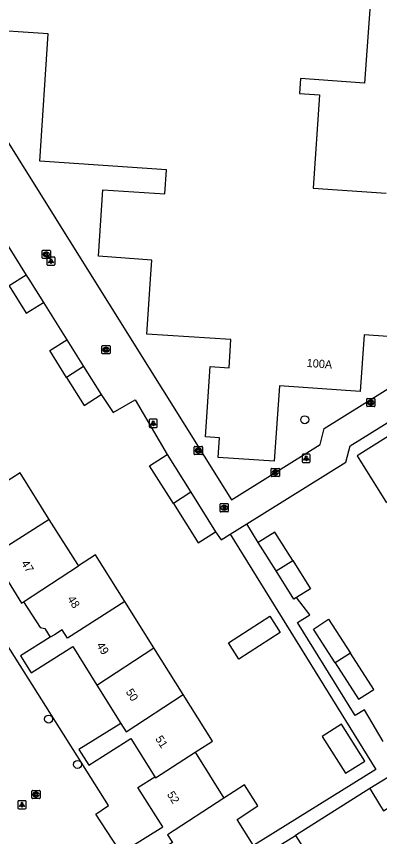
# Model space of a CAD drawing. Extents: x 158461 to 159795, y 387220 to 388672.
# Drawn here: x 158888.2 to 158932.6, y 387931.9 to 388032.1 of the extents above; entities that cross this region are included whole.
import ezdxf

# ---------------------------------------------------------------- set-up
doc = ezdxf.new("R2010")
doc.units = 0
for name, color, linetype in [('IMGEO_Boom', 7, 'Continuous'), ('IMGEO_Kolk', 7, 'Continuous'), ('IMGEO_Lichtpunt', 7, 'Continuous'), ('IMGEO_Pand', 7, 'Continuous'), ('IMGEO_Pand_nummerreeks', 7, 'Continuous'), ('IMGEO_Rijbaan_lokaal_open', 7, 'Continuous'), ('IMGEO_Rioolput', 7, 'Continuous'), ('IMGEO_Voetpad_open', 7, 'Continuous')]:
    doc.layers.add(name, color=color, linetype=linetype)

msp = doc.modelspace()

# ---------------------------------------------------------------- linework, layer by layer
at = {"layer": 'IMGEO_Boom'}
for centre in [(158923.44, 387982.83), (158892.12, 387946.23), (158895.66, 387940.69)]:
    msp.add_circle(centre, 0.489, dxfattribs=at)
at = {"layer": 'IMGEO_Kolk'}
for p, q in [((158891.34, 388002.62), (158891.34, 388003.48)), ((158891.41, 388003.55), (158892.27, 388003.55)), ((158891.85, 388002.77), (158891.82, 388002.77)), ((158891.83, 388003.33), (158891.85, 388003.33)), ((158892.34, 388003.48), (158892.34, 388002.62)), ((158892.27, 388002.55), (158891.41, 388002.55)), ((158898.65, 387990.96), (158898.65, 387991.82)), ((158898.72, 387991.89), (158899.57, 387991.89)), ((158899.13, 387991.67), (158899.16, 387991.67)), ((158899.65, 387991.82), (158899.65, 387990.96)), ((158899.57, 387990.89), (158898.72, 387990.89)), ((158899.16, 387991.11), (158899.13, 387991.11)), ((158931.02, 387984.51), (158931.02, 387985.36)), ((158931.1, 387985.44), (158931.95, 387985.44)), ((158931.51, 387985.21), (158931.54, 387985.21)), ((158931.53, 387984.66), (158931.51, 387984.66)), ((158932.02, 387985.36), (158932.02, 387984.51)), ((158931.95, 387984.43), (158931.1, 387984.43)), ((158910.02, 387979.57), (158910.87, 387979.57)), ((158909.94, 387978.64), (158909.94, 387979.49)), ((158910.87, 387978.57), (158910.02, 387978.57)), ((158910.43, 387979.35), (158910.45, 387979.35)), ((158910.45, 387978.79), (158910.43, 387978.79)), ((158910.94, 387979.49), (158910.94, 387978.64)), ((158919.35, 387975.95), (158919.35, 387976.81)), ((158919.42, 387976.88), (158920.28, 387976.88)), ((158919.84, 387976.66), (158919.86, 387976.66)), ((158920.35, 387976.81), (158920.35, 387975.95)), ((158920.28, 387975.88), (158919.42, 387975.88)), ((158919.86, 387976.1), (158919.83, 387976.1)), ((158890.08, 387936.59), (158890.08, 387937.44)), ((158890.15, 387937.52), (158891.01, 387937.52)), ((158891.08, 387937.44), (158891.08, 387936.59)), ((158891.01, 387936.52), (158890.15, 387936.52)), ((158890.59, 387936.74), (158890.56, 387936.74)), ((158890.57, 387937.3), (158890.59, 387937.3))]:
    msp.add_line(p, q, dxfattribs=at)
for points in [[(158891.34, 388002.62), (158891.34, 388003.48)], [(158891.41, 388003.55), (158892.27, 388003.55)], [(158891.66, 388003.25), (158891.78, 388003.25), (158891.78, 388003.1), (158891.91, 388003.25), (158892.08, 388003.25), (158891.93, 388003.1), (158892.08, 388002.85), (158891.93, 388002.85), (158891.85, 388003.01), (158891.78, 388002.95), (158891.78, 388002.85), (158891.66, 388002.85), (158891.66, 388003.25)], [(158892.34, 388003.48), (158892.34, 388002.62)], [(158892.27, 388002.55), (158891.41, 388002.55)], [(158898.65, 387990.96), (158898.65, 387991.82)], [(158898.72, 387991.89), (158899.57, 387991.89)], [(158898.97, 387991.59), (158899.09, 387991.59), (158899.09, 387991.44), (158899.22, 387991.59), (158899.38, 387991.59), (158899.24, 387991.44), (158899.39, 387991.19), (158899.24, 387991.19), (158899.15, 387991.36), (158899.09, 387991.29), (158899.09, 387991.19), (158898.97, 387991.19), (158898.97, 387991.59)], [(158899.65, 387991.82), (158899.65, 387990.96)], [(158899.57, 387990.89), (158898.72, 387990.89)], [(158931.02, 387984.51), (158931.02, 387985.36)], [(158931.1, 387985.44), (158931.95, 387985.44)], [(158931.34, 387985.13), (158931.47, 387985.13), (158931.47, 387984.98), (158931.6, 387985.13), (158931.76, 387985.13), (158931.61, 387984.98), (158931.77, 387984.73), (158931.61, 387984.73), (158931.53, 387984.9), (158931.47, 387984.83), (158931.47, 387984.73), (158931.34, 387984.73), (158931.34, 387985.13)], [(158932.02, 387985.36), (158932.02, 387984.51)], [(158931.95, 387984.43), (158931.1, 387984.43)], [(158910.02, 387979.57), (158910.87, 387979.57)], [(158909.94, 387978.64), (158909.94, 387979.49)], [(158910.87, 387978.57), (158910.02, 387978.57)], [(158910.26, 387979.27), (158910.39, 387979.27), (158910.39, 387979.12), (158910.51, 387979.27), (158910.68, 387979.27), (158910.53, 387979.12), (158910.69, 387978.87), (158910.53, 387978.87), (158910.45, 387979.03), (158910.39, 387978.96), (158910.39, 387978.87), (158910.26, 387978.87), (158910.26, 387979.27)], [(158910.94, 387979.49), (158910.94, 387978.64)], [(158919.35, 387975.95), (158919.35, 387976.81)], [(158919.42, 387976.88), (158920.28, 387976.88)], [(158919.67, 387976.58), (158919.79, 387976.58), (158919.79, 387976.43), (158919.92, 387976.58), (158920.09, 387976.58), (158919.94, 387976.43), (158920.09, 387976.18), (158919.94, 387976.18), (158919.86, 387976.35), (158919.79, 387976.28), (158919.79, 387976.18), (158919.67, 387976.18), (158919.67, 387976.58)], [(158920.35, 387976.81), (158920.35, 387975.95)], [(158920.28, 387975.88), (158919.42, 387975.88)], [(158890.08, 387936.59), (158890.08, 387937.44)], [(158890.15, 387937.52), (158891.01, 387937.52)], [(158891.08, 387937.44), (158891.08, 387936.59)], [(158891.01, 387936.52), (158890.15, 387936.52)], [(158890.4, 387937.22), (158890.52, 387937.22), (158890.52, 387937.07), (158890.65, 387937.22), (158890.82, 387937.22), (158890.67, 387937.07), (158890.82, 387936.82), (158890.67, 387936.82), (158890.59, 387936.98), (158890.52, 387936.92), (158890.52, 387936.82), (158890.4, 387936.82), (158890.4, 387937.22)]]:
    msp.add_lwpolyline(points, dxfattribs=at)
for centre, start, end in [((158891.42, 388003.47), 91.552, 178.448), ((158891.42, 388003.47), 91.552, 178.448), ((158891.42, 388002.63), 181.552, 268.448), ((158891.42, 388002.63), 181.552, 268.448), ((158892.26, 388003.47), 1.552, 88.448), ((158892.26, 388003.47), 1.552, 88.448), ((158892.26, 388002.63), 271.552, 358.448), ((158892.26, 388002.63), 271.552, 358.448), ((158898.72, 387991.82), 91.552, 178.448), ((158898.72, 387991.82), 91.552, 178.448), ((158899.57, 387991.82), 1.552, 88.448), ((158899.57, 387991.82), 1.552, 88.448), ((158898.72, 387990.97), 181.552, 268.448), ((158898.72, 387990.97), 181.552, 268.448), ((158899.57, 387990.97), 271.552, 358.448), ((158899.57, 387990.97), 271.552, 358.448), ((158931.1, 387985.36), 91.552, 178.448), ((158931.1, 387985.36), 91.552, 178.448), ((158931.95, 387985.36), 1.552, 88.448), ((158931.95, 387985.36), 1.552, 88.448), ((158931.1, 387984.51), 181.552, 268.448), ((158931.1, 387984.51), 181.552, 268.448), ((158931.95, 387984.51), 271.552, 358.448), ((158931.95, 387984.51), 271.552, 358.448), ((158910.02, 387979.49), 91.552, 178.448), ((158910.02, 387979.49), 91.552, 178.448), ((158910.87, 387979.49), 1.552, 88.448), ((158910.87, 387979.49), 1.552, 88.448), ((158910.02, 387978.64), 181.552, 268.448), ((158910.02, 387978.64), 181.552, 268.448), ((158910.87, 387978.64), 271.552, 358.448), ((158910.87, 387978.64), 271.552, 358.448), ((158919.43, 387976.81), 91.552, 178.448), ((158919.43, 387976.81), 91.552, 178.448), ((158920.27, 387976.81), 1.552, 88.448), ((158920.27, 387976.81), 1.552, 88.448), ((158919.43, 387975.96), 181.552, 268.448), ((158919.43, 387975.96), 181.552, 268.448), ((158920.27, 387975.96), 271.552, 358.448), ((158920.27, 387975.96), 271.552, 358.448), ((158890.15, 387937.44), 91.552, 178.448), ((158890.15, 387937.44), 91.552, 178.448), ((158891, 387937.44), 1.552, 88.448), ((158891, 387937.44), 1.552, 88.448), ((158890.15, 387936.59), 181.552, 268.448), ((158890.15, 387936.59), 181.552, 268.448), ((158891, 387936.59), 271.552, 358.448), ((158891, 387936.59), 271.552, 358.448)]:
    msp.add_arc(centre, 0.0765, start, end, dxfattribs=at)
for centre, major_axis, ratio, start_param, end_param in [((158891.83, 388003.05), (-0.387, 0.002), 0.722429, 4.712389, 7.853982), ((158891.85, 388003.05), (-0.39, 0.002), 0.717154, 1.570796, 4.712389), ((158899.13, 387991.39), (-0.387, 0.002), 0.722429, 4.712389, 7.853982), ((158899.16, 387991.39), (-0.39, 0.002), 0.717154, 1.570796, 4.712389), ((158931.51, 387984.93), (-0.387, 0.002), 0.722429, 4.712389, 7.853982), ((158931.53, 387984.93), (-0.39, 0.002), 0.717154, 1.570796, 4.712389), ((158910.43, 387979.07), (-0.387, 0.002), 0.722429, 4.712389, 7.853982), ((158910.45, 387979.07), (-0.39, 0.002), 0.717154, 1.570796, 4.712389), ((158919.84, 387976.38), (-0.387, 0.002), 0.722429, 4.712389, 7.853982), ((158919.86, 387976.38), (-0.39, 0.002), 0.717154, 1.570796, 4.712389), ((158890.57, 387937.02), (-0.387, 0.002), 0.722429, 4.712389, 7.853982), ((158890.59, 387937.02), (-0.39, 0.002), 0.717154, 1.570796, 4.712389)]:
    msp.add_ellipse(centre, major_axis=major_axis, ratio=ratio, start_param=start_param, end_param=end_param, dxfattribs=at)
at = {"layer": 'IMGEO_Lichtpunt'}
for p, q in [((158891.91, 388002.62), (158891.91, 388001.82)), ((158891.91, 388002.62), (158891.91, 388001.82)), ((158892.81, 388002.72), (158892.01, 388002.72)), ((158892.81, 388002.72), (158892.01, 388002.72)), ((158892.91, 388001.82), (158892.91, 388002.62)), ((158892.91, 388001.82), (158892.91, 388002.62)), ((158892.01, 388001.72), (158892.81, 388001.72)), ((158892.01, 388001.72), (158892.81, 388001.72)), ((158904.42, 387982.8), (158904.42, 387981.99)), ((158904.42, 387982.8), (158904.42, 387981.99)), ((158905.32, 387982.89), (158904.51, 387982.89)), ((158905.32, 387982.89), (158904.51, 387982.89)), ((158905.42, 387981.99), (158905.42, 387982.8)), ((158905.42, 387981.99), (158905.42, 387982.8)), ((158904.51, 387981.9), (158905.32, 387981.9)), ((158904.51, 387981.9), (158905.32, 387981.9)), ((158924.02, 387978.61), (158923.22, 387978.61)), ((158924.02, 387978.61), (158923.22, 387978.61)), ((158923.12, 387978.51), (158923.12, 387977.71)), ((158923.12, 387978.51), (158923.12, 387977.71)), ((158923.22, 387977.61), (158924.02, 387977.61)), ((158923.22, 387977.61), (158924.02, 387977.61)), ((158924.12, 387977.71), (158924.12, 387978.51)), ((158924.12, 387977.71), (158924.12, 387978.51)), ((158888.38, 387936.16), (158888.38, 387935.36)), ((158888.38, 387936.16), (158888.38, 387935.36)), ((158889.28, 387936.26), (158888.47, 387936.26)), ((158889.28, 387936.26), (158888.47, 387936.26)), ((158889.38, 387935.36), (158889.38, 387936.16)), ((158889.38, 387935.36), (158889.38, 387936.16)), ((158888.47, 387935.26), (158889.28, 387935.26)), ((158888.47, 387935.26), (158889.28, 387935.26))]:
    msp.add_line(p, q, dxfattribs=at)
for points in [[(158892.29, 388002.29), (158892.33, 388002.26), (158892.14, 388002), (158892.1, 388002.03), (158892.29, 388002.29)], [(158892.39, 388002.24), (158892.44, 388002.24), (158892.44, 388001.92), (158892.39, 388001.92), (158892.39, 388002.24)], [(158892.5, 388002.26), (158892.54, 388002.29), (158892.72, 388002.02), (158892.69, 388002), (158892.5, 388002.26)], [(158904.79, 387982.46), (158904.83, 387982.43), (158904.65, 387982.17), (158904.61, 387982.2), (158904.79, 387982.46)], [(158904.9, 387982.41), (158904.94, 387982.41), (158904.94, 387982.09), (158904.9, 387982.09), (158904.9, 387982.41)], [(158905.01, 387982.43), (158905.04, 387982.46), (158905.23, 387982.2), (158905.19, 387982.17), (158905.01, 387982.43)], [(158923.5, 387978.18), (158923.54, 387978.15), (158923.35, 387977.89), (158923.31, 387977.91), (158923.5, 387978.18)], [(158923.6, 387978.13), (158923.65, 387978.13), (158923.65, 387977.81), (158923.6, 387977.81), (158923.6, 387978.13)], [(158923.71, 387978.15), (158923.75, 387978.18), (158923.93, 387977.91), (158923.9, 387977.89), (158923.71, 387978.15)], [(158888.75, 387935.83), (158888.79, 387935.8), (158888.6, 387935.54), (158888.57, 387935.56), (158888.75, 387935.83)], [(158888.85, 387935.78), (158888.9, 387935.78), (158888.9, 387935.46), (158888.85, 387935.46), (158888.85, 387935.78)], [(158888.96, 387935.8), (158889, 387935.83), (158889.19, 387935.56), (158889.15, 387935.54), (158888.96, 387935.8)]]:
    msp.add_lwpolyline(points, dxfattribs=at)
for centre in [(158892.41, 388002.42), (158904.92, 387982.6), (158923.62, 387978.31), (158888.88, 387935.96)]:
    msp.add_circle(centre, 0.0994, dxfattribs=at)
for centre, start, end in [((158892.01, 388002.62), 90, 180), ((158892.01, 388002.62), 90, 180), ((158892.81, 388002.62), 0, 90), ((158892.81, 388002.62), 0, 90), ((158892.01, 388001.82), 180, 270), ((158892.01, 388001.82), 180, 270), ((158892.81, 388001.82), 270, 0), ((158892.81, 388001.82), 270, 360), ((158904.51, 387982.8), 90, 180), ((158904.51, 387982.8), 90, 180), ((158905.32, 387982.8), 0, 90), ((158905.32, 387982.8), 0, 90), ((158904.51, 387981.99), 180, 270), ((158904.51, 387981.99), 180, 270), ((158905.32, 387981.99), 270, 0), ((158905.32, 387981.99), 270, 360), ((158923.22, 387978.51), 90, 180), ((158923.22, 387978.51), 90, 180), ((158924.02, 387978.51), 0, 90), ((158924.02, 387978.51), 0, 90), ((158923.22, 387977.71), 180, 270), ((158923.22, 387977.71), 180, 270), ((158924.02, 387977.71), 270, 0), ((158924.02, 387977.71), 270, 360), ((158888.47, 387936.16), 90, 180), ((158888.47, 387936.16), 90, 180), ((158889.28, 387936.16), 0, 90), ((158889.28, 387936.16), 0, 90), ((158888.47, 387935.36), 180, 270), ((158888.47, 387935.36), 180, 270), ((158889.28, 387935.36), 270, 0), ((158889.28, 387935.36), 270, 360)]:
    msp.add_arc(centre, 0.0946, start, end, dxfattribs=at)
at = {"layer": 'IMGEO_Pand'}
for points in [[(158931.89, 388039.84), (158930.75, 388023.98)], [(158940.55, 387992.52), (158930.7, 387993.22), (158930.21, 387986.3), (158920.36, 387986.99), (158919.71, 387977.75), (158912.85, 387978.23), (158913.01, 387980.61), (158911.29, 387980.73), (158911.9, 387989.32), (158914.19, 387989.16), (158914.42, 387992.64), (158904.14, 387993.31), (158904.58, 388000), (158904.74, 388002.35), (158898.21, 388002.82), (158898.76, 388010.94), (158906.33, 388010.43), (158906.55, 388013.39), (158891.04, 388014.45), (158892.07, 388030.01), (158883.53, 388030.56)], [(158930.75, 388023.98), (158922.93, 388024.56), (158922.8, 388022.72), (158925.26, 388022.53), (158924.47, 388011.14), (158933.39, 388010.52)], [(158887.17, 388004.03), (158889.38, 388000.51)], [(158889.38, 388000.51), (158887.3, 387999.19)], [(158889.38, 388000.51), (158889.7, 388000), (158891.49, 387997.15)], [(158887.3, 387999.19), (158889.4, 387995.84), (158891.49, 387997.15)], [(158894.32, 387988.01), (158892.26, 387991.29), (158894.36, 387992.6)], [(158894.36, 387992.6), (158896.4, 387989.35)], [(158896.4, 387989.35), (158894.32, 387988.01)], [(158896.4, 387989.35), (158898.57, 387985.91)], [(158894.32, 387988.01), (158896.47, 387984.59), (158898.57, 387985.91)], [(158940.49, 387977.03), (158936.85, 387982.81), (158929.85, 387978.4), (158933.45, 387972.68)], [(158907.39, 387972.57), (158904.47, 387977.21), (158906.62, 387978.56)], [(158906.62, 387978.56), (158909.51, 387973.96)], [(158892.21, 387970.65), (158888.64, 387976.33), (158886.62, 387975.02)], [(158909.51, 387973.96), (158907.39, 387972.57)], [(158909.51, 387973.96), (158912.55, 387969.12)], [(158907.39, 387972.57), (158910.4, 387967.77), (158912.55, 387969.12)], [(158892.21, 387970.65), (158885.17, 387966.2), (158885.82, 387965.16)], [(158895.78, 387964.96), (158895.68, 387965.12), (158892.21, 387970.65)], [(158921.97, 387965.61), (158919.79, 387969.08), (158917.77, 387967.82)], [(158919.94, 387964.35), (158917.77, 387967.82)], [(158901.43, 387960.62), (158897.85, 387966.31), (158895.78, 387964.96)], [(158919.94, 387964.35), (158921.97, 387965.61)], [(158921.97, 387965.61), (158924.13, 387962.17), (158922.44, 387961.1)], [(158885.82, 387965.16), (158888.8, 387960.42), (158889.04, 387960.58)], [(158889.04, 387960.58), (158895.78, 387964.96)], [(158922.44, 387961.1), (158922.11, 387960.9), (158919.94, 387964.35)], [(158889.04, 387960.58), (158891.08, 387957.44), (158891.65, 387957.3), (158892.32, 387956.23)], [(158901.43, 387960.62), (158894.42, 387956.13), (158893.78, 387957.15), (158892.83, 387956.55), (158892.32, 387956.23)], [(158905, 387954.93), (158901.43, 387960.62)], [(158919.16, 387958.81), (158920.44, 387956.84), (158915.39, 387953.57), (158914.11, 387955.55), (158919.16, 387958.81)], [(158927.15, 387953.13), (158924.5, 387957.24), (158926.37, 387958.45), (158929.05, 387954.29)], [(158892.32, 387956.23), (158888.69, 387953.95), (158889.98, 387951.89), (158895.07, 387955.09), (158898.02, 387950.39)], [(158898.02, 387950.39), (158905, 387954.93)], [(158908.57, 387949.25), (158905, 387954.93)], [(158929.05, 387954.29), (158927.15, 387953.13)], [(158927.15, 387953.13), (158930.03, 387948.67), (158931.9, 387949.87), (158929.05, 387954.29)], [(158898.02, 387950.39), (158900.96, 387945.71)], [(158900.96, 387945.71), (158901.6, 387944.68), (158908.57, 387949.25)], [(158910.03, 387942.18), (158912.17, 387943.53), (158908.57, 387949.25)], [(158900.96, 387945.71), (158895.84, 387942.5), (158897.03, 387940.61), (158902.17, 387943.85), (158905.11, 387939.17)], [(158925.59, 387944.12), (158928.44, 387939.61), (158930.8, 387941.11), (158927.96, 387945.61), (158925.59, 387944.12)], [(158905.11, 387939.17), (158905.18, 387939.06), (158910.03, 387942.18)], [(158910.03, 387942.18), (158913.56, 387936.56)], [(158935.28, 387940.13), (158931.41, 387937.73)], [(158907.29, 387931.15), (158902.98, 387928.44), (158901.78, 387930.36), (158906.08, 387933.06), (158903.05, 387937.88), (158905.11, 387939.17)], [(158917.18, 387930.8), (158915.18, 387933.97), (158917.72, 387935.62), (158916.06, 387938.18), (158913.56, 387936.56)], [(158931.41, 387937.73), (158932.7, 387935.58), (158933.09, 387935.01), (158936.93, 387937.43)], [(158913.56, 387936.56), (158906.68, 387932.1), (158907.29, 387931.15)], [(158918.05, 387929.35), (158922.32, 387932.01)], [(158922.32, 387932.01), (158923.44, 387930.22), (158919.18, 387927.56)]]:
    msp.add_lwpolyline(points, dxfattribs=at)
at = {"layer": 'IMGEO_Rijbaan_lokaal_open'}
msp.add_lwpolyline([(158905.27, 387923.32), (158897.89, 387934.62), (158899.45, 387935.66), (158885.25, 387958.08), (158883.81, 387957.28), (158876.89, 387968.59), (158875.93, 387968.06), (158866.63, 387982.91), (158867.51, 387983.39), (158862.42, 387991.59)], dxfattribs=at)
at = {"layer": 'IMGEO_Rioolput'}
for p, q in [((158913.17, 387972.57), (158914.02, 387972.57)), ((158913.1, 387971.64), (158913.1, 387972.49)), ((158914.02, 387971.57), (158913.17, 387971.57)), ((158913.58, 387972.35), (158913.61, 387972.35)), ((158913.61, 387971.79), (158913.58, 387971.79)), ((158914.1, 387972.49), (158914.1, 387971.64))]:
    msp.add_line(p, q, dxfattribs=at)
for points in [[(158913.17, 387972.57), (158914.02, 387972.57)], [(158913.1, 387971.64), (158913.1, 387972.49)], [(158914.02, 387971.57), (158913.17, 387971.57)], [(158913.69, 387972.26), (158913.43, 387972.27), (158913.43, 387971.87)], [(158913.43, 387971.87), (158913.56, 387971.87), (158913.56, 387972.03), (158913.57, 387972.03)], [(158913.61, 387972.19), (158913.56, 387972.19), (158913.56, 387972.1)], [(158913.56, 387972.1), (158913.61, 387972.1)], [(158913.61, 387972), (158913.69, 387971.87), (158913.83, 387971.87), (158913.76, 387971.99)], [(158914.1, 387972.49), (158914.1, 387971.64)]]:
    msp.add_lwpolyline(points, dxfattribs=at)
for centre, radius, start, end in [((158913.17, 387972.49), 0.0765, 91.552, 178.448), ((158913.17, 387972.49), 0.0765, 91.552, 178.448), ((158914.02, 387972.49), 0.0765, 1.552, 88.448), ((158914.02, 387972.49), 0.0765, 1.552, 88.448), ((158913.17, 387971.64), 0.0765, 181.552, 268.448), ((158913.17, 387971.64), 0.0765, 181.552, 268.448), ((158913.57, 387971.98), 0.0533, 26.0293, 88.6989), ((158913.62, 387972.09), 0.0964, 77.0061, 93.1865), ((158913.59, 387972.29), 0.19, 274.7715, 282.9687), ((158913.63, 387972.15), 0.0378, 276.6634, 79.6772), ((158913.68, 387972.16), 0.109, 350.3612, 89.416), ((158913.68, 387972.15), 0.112, 277.5842, 350.9817), ((158913.67, 387971.94), 0.108, 29.5134, 73.7905), ((158914.02, 387971.64), 0.0765, 271.552, 358.448), ((158914.02, 387971.64), 0.0765, 271.552, 358.448)]:
    msp.add_arc(centre, radius, start, end, dxfattribs=at)
for centre, major_axis, ratio, start_param, end_param in [((158913.58, 387972.07), (-0.387, 0.002), 0.722429, 4.712389, 7.853982), ((158913.61, 387972.07), (-0.39, 0.002), 0.717154, 1.570796, 4.712389)]:
    msp.add_ellipse(centre, major_axis=major_axis, ratio=ratio, start_param=start_param, end_param=end_param, dxfattribs=at)
at = {"layer": 'IMGEO_Voetpad_open'}
for points in [[(158874.56, 388036.95), (158897.61, 388000), (158914.5, 387973.05), (158925.33, 387979.79), (158925.8, 387981.75), (158937.6, 387989.08)], [(158891.49, 387997.15), (158894.36, 387992.6)], [(158898.57, 387985.91), (158900.03, 387983.7), (158902.71, 387985.25), (158906.62, 387978.56)], [(158916.38, 387970.11), (158928.45, 387977.65), (158928.99, 387979.65), (158939.44, 387986.12)], [(158914.33, 387968.83), (158916.38, 387970.11)], [(158917.77, 387967.82), (158916.38, 387970.11)], [(158912.55, 387969.12), (158913.23, 387968.15), (158914.33, 387968.83)], [(158914.33, 387968.83), (158932.15, 387940.09), (158917.18, 387930.8)], [(158933.04, 387943.51), (158930.75, 387947.38), (158929.61, 387946.66), (158922.55, 387958.04), (158924.06, 387958.98), (158922.44, 387961.1)], [(158931.41, 387937.73), (158922.32, 387932.01)]]:
    msp.add_lwpolyline(points, dxfattribs=at)

# ---------------------------------------------------------------- texts
at = {"layer": 'IMGEO_Pand_nummerreeks'}
for s, rotation, p in [('100A', 355.9739, (158923.65, 387989.29)), ('47', 302.0167, (158888.74, 387965.28)), ('48', 302.1198, (158894.38, 387960.93)), ('49', 302.1198, (158897.94, 387955.25)), ('50', 302.1188, (158901.52, 387949.57)), ('51', 302.4455, (158905.13, 387943.83)), ('52', 302.1897, (158906.56, 387937.03))]:
    msp.add_text(s, height=1, rotation=rotation, dxfattribs=at).set_placement(p)

doc.saveas('drawing.dxf')
